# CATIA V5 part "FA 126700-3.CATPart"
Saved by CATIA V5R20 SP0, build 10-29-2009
Part number: FA 126700-3
Revision: ANY
Definition: UNKNOWN
Nomenclature: FA 126700-3
Source: Unknown
Bounding box of the stored display mesh (mm): x -3.264 to 3.264, y -2.475 to 2.475, z -3 to 3
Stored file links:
  C:\Users\Utente\Desktop\IO LAVORO\3D X SITO CF\CUMSA\3D files FA\FA 1267SF\FA 126700-3.CATPart

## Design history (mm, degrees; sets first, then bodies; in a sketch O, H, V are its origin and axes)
Body1 "Chaflán4" (main body)
  Solid1: solid without history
